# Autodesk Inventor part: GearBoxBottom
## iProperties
Part Number: GearBoxBottom
Document SubType Name: Modeling
Created: 2003-11
Designer: ales
Manufacturer: Standard
Standards Organization: Custom
Density: 1 g/cm^3
Mass: 992.934 g
Surface Area: 1851.36 cm^2
Volume: 992.934 cm^3
Control State: 0
Master: False
Checked Out: False
Shininess: 64.0
Length Units: 11269
Angle Units: 11279
Time Units: 11290
Mass Units: 11283
Length Display Precision: 3
Angle Display Precision: 2
Compacted: True
Density: 0.0
Volumn: 0.0
Area: 0.0
PropertySet Name: Model Information
Author: ales
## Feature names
1. Main Body [Extrusion]
2. Shell1
3. Arrow [Extrusion]
4. Extrusion15
5. Extrusion13
6. Extrusion3
7. Extrusion4
8. Extrusion5
9. Extrusion6
10. Extrusion7
11. Hole2
12. Rectangular Pattern1
13. Bearing Holder Output [Extrusion]
14. Extrusion18
15. Bearing Holder Input [Extrusion]
16. Extrusion20
17. Extrusion21
18. Extrusion22
19. Extrusion23
20. Extrusion24
21. Fillet1
22. Fillet2
23. Fillet3
24. Fillet4
25. Fillet5
26. Fillet6
27. Fillet8
28. Fillet9
29. Chamfer1
30. Chamfer2
31. Fillet11
32. Hole3
33. Hole4
34. Hole5
35. Hole6
36. Hole7
37. Hole8
38. Fillet12
39. Fillet13
40. Extrusion26
41. Extrusion27
42. Extrusion28
43. Hole9
44. Circular Pattern1
45. Fillet14
46. Fillet15
47. Chamfer4
